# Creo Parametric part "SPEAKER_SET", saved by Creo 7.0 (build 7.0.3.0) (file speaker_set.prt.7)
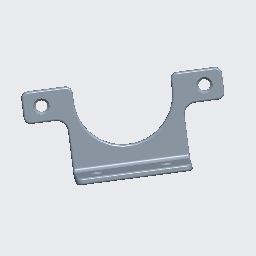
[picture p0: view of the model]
Units: millimeter Kilogram Sec (mmKs); MM, KILOGRAM, SECS

Created from: XX_SOLID_PART_MMKS_ABS.PRT

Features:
  1. coordinate system
  2. datum plane "RIGHT"
  3. datum plane "TOP"
  4. datum plane "FRONT"
  5. extrusion "Extrude 1"
  6. extrusion "Extrude 2"
  7. extruded cut "Extrude 3"
  8. extruded cut "Extrude 4"
  9. extruded cut "Extrude 5"
  10. round "Round 1"
  11. round "Round 2"
  12. round "Round 3"
  13. chamfer "Chamfer 1"
  14. round "Round 4"
  15. chamfer "Chamfer 2"

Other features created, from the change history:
  round "Round 3"
  round "Round 4"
